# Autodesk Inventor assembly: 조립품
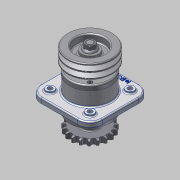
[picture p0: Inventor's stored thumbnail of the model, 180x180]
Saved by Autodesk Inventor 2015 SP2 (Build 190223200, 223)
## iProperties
Created: 2015-07
Part Number: 조립품
Document SubType Name: Assembly
Designer: AMC
Author: AMC
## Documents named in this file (12)
- C:\Users\AMC\Desktop\450735V1003\조립품.iam
- C:\Users\AMC\Desktop\450735V1003\본체.ipt
- C:\Users\AMC\Desktop\450735V1003\2-커버.ipt
- C:\Users\AMC\Desktop\450735V1003\3-축.ipt
- C:\Users\AMC\Desktop\450735V1003\4-V벨트풀리.ipt
- C:\Users\AMC\Desktop\450735V1003\5-체인 스프로킷.ipt
- C:\Users\AMC\Desktop\450735V1003\6-베어링 6206.ipt
- C:\Users\AMC\Desktop\450735V1003\7-부시.ipt
- C:\Users\AMC\Desktop\450735V1003\8-오일실 30x42.ipt
- C:\Users\AMC\Desktop\450735V1003\9-M16-너트.ipt
- C:\Users\AMC\Desktop\450735V1003\10-M6.ipt
- C:\Users\AMC\Desktop\450735V1003\11-키 6x6.ipt
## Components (22 placed, 10 different names)
1. 2-커버:1
2. 3-축:1
3. 4-V벨트풀리:1 — 각도:1
4. 5-체인 스프로킷:1 — 각도:2
5. 6-베어링 6206:1
6. 7-부시:1
7. 8-8-오일실 30x42:1
8. 9-M16 너트:1
9. 11-키 6x6:1 — 각도:1
10. 6-베어링 6206:2
11. 2-커버:2
12. 11-키 6x6:2 — 각도:2
13. 8-8-오일실 30x42:2
14. 9-M16 너트:2
15. 10-M6:1
16. 10-M6:3
17. 10-M6:4
18. 10-M6:5
19. 10-M6:2
20. 10-M6:6
21. 10-M6:7
22. 10-M6:8
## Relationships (2: Angle 2)
- 각도:1 [Angle]: 4-V벨트풀리:1 ↔ 11-키 6x6:1
- 각도:2 [Angle]: 5-체인 스프로킷:1 ↔ 11-키 6x6:2
